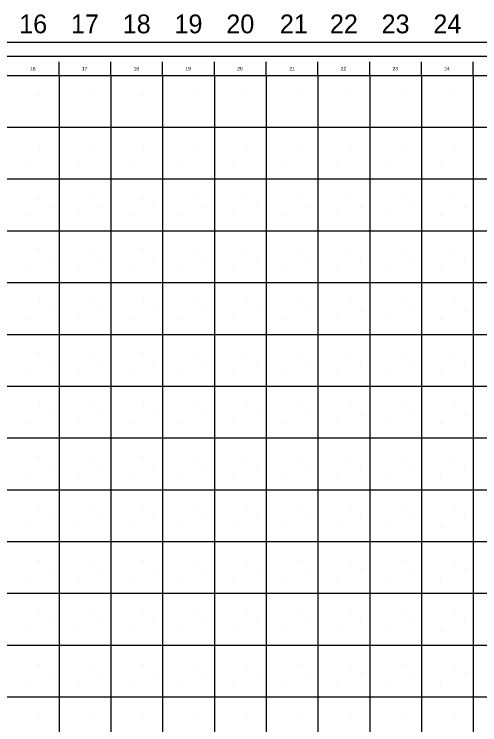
# Model space of a CAD drawing. Extents: x -0.05 to 1.19, y 0 to 0.86.
# Drawn here: x 0.5647 to 0.8795, y 0.3796 to 0.8598 of the extents above; entities that cross this region are included whole.
import ezdxf

# ---------------------------------------------------------------- set-up
doc = ezdxf.new("R2010")
doc.units = 0
for name, color, linetype in [('G-ANNO-NPLT', 7, 'Continuous'), ('G-ANNO-TEXT', 7, 'Continuous'), ('G-ANNO-TTLB', 7, 'Continuous'), ('G-ANNO-TTLB-GRID', 7, 'Continuous')]:
    doc.layers.add(name, color=color, linetype=linetype)

msp = doc.modelspace()

# ---------------------------------------------------------------- linework, layer by layer
at = {"layer": 'G-ANNO-NPLT'}
for p, q in [((0.58208, 0.80547), (0.58208, 0.80547)), ((0.61707, 0.80547), (0.61707, 0.80547)), ((0.65207, 0.80547), (0.65207, 0.80547)), ((0.68707, 0.80547), (0.68707, 0.80547)), ((0.72208, 0.80547), (0.72208, 0.80547)), ((0.75707, 0.80547), (0.75707, 0.80547)), ((0.79207, 0.80547), (0.79207, 0.80547)), ((0.82708, 0.80547), (0.82708, 0.80547)), ((0.86207, 0.80547), (0.86207, 0.80547)), ((0.58208, 0.77047), (0.58208, 0.77047)), ((0.61707, 0.77047), (0.61707, 0.77047)), ((0.65207, 0.77047), (0.65207, 0.77047)), ((0.68707, 0.77047), (0.68707, 0.77047)), ((0.72208, 0.77047), (0.72208, 0.77047)), ((0.75707, 0.77047), (0.75707, 0.77047)), ((0.79207, 0.77047), (0.79207, 0.77047)), ((0.82708, 0.77047), (0.82708, 0.77047)), ((0.86207, 0.77047), (0.86207, 0.77047)), ((0.57308, 0.75847), (0.57308, 0.75847)), ((0.60807, 0.75847), (0.60807, 0.75847)), ((0.64307, 0.75847), (0.64307, 0.75847)), ((0.67807, 0.75847), (0.67807, 0.75847)), ((0.71308, 0.75847), (0.71308, 0.75847)), ((0.74807, 0.75847), (0.74807, 0.75847)), ((0.78307, 0.75847), (0.78307, 0.75847)), ((0.81807, 0.75847), (0.81807, 0.75847)), ((0.85307, 0.75847), (0.85307, 0.75847)), ((0.58208, 0.73547), (0.58208, 0.73547)), ((0.61707, 0.73547), (0.61707, 0.73547)), ((0.65207, 0.73547), (0.65207, 0.73547)), ((0.68707, 0.73547), (0.68707, 0.73547)), ((0.72208, 0.73547), (0.72208, 0.73547)), ((0.75707, 0.73547), (0.75707, 0.73547)), ((0.79207, 0.73547), (0.79207, 0.73547)), ((0.82708, 0.73547), (0.82708, 0.73547)), ((0.86207, 0.73547), (0.86207, 0.73547)), ((0.58908, 0.72947), (0.58908, 0.72947)), ((0.62407, 0.72947), (0.62407, 0.72947)), ((0.65907, 0.72947), (0.65907, 0.72947)), ((0.69407, 0.72947), (0.69407, 0.72947)), ((0.72907, 0.72947), (0.72907, 0.72947)), ((0.76407, 0.72947), (0.76407, 0.72947)), ((0.79907, 0.72947), (0.79907, 0.72947)), ((0.83408, 0.72947), (0.83408, 0.72947)), ((0.86907, 0.72947), (0.86907, 0.72947)), ((0.57308, 0.72347), (0.57308, 0.72347)), ((0.60807, 0.72347), (0.60807, 0.72347)), ((0.64307, 0.72347), (0.64307, 0.72347)), ((0.67807, 0.72347), (0.67807, 0.72347)), ((0.71308, 0.72347), (0.71308, 0.72347)), ((0.74807, 0.72347), (0.74807, 0.72347)), ((0.78307, 0.72347), (0.78307, 0.72347)), ((0.81807, 0.72347), (0.81807, 0.72347)), ((0.85307, 0.72347), (0.85307, 0.72347)), ((0.58208, 0.70047), (0.58208, 0.70047)), ((0.61707, 0.70047), (0.61707, 0.70047)), ((0.65207, 0.70047), (0.65207, 0.70047)), ((0.68707, 0.70047), (0.68707, 0.70047)), ((0.72208, 0.70047), (0.72208, 0.70047)), ((0.75707, 0.70047), (0.75707, 0.70047)), ((0.79207, 0.70047), (0.79207, 0.70047)), ((0.82708, 0.70047), (0.82708, 0.70047)), ((0.86207, 0.70047), (0.86207, 0.70047)), ((0.58908, 0.69447), (0.58908, 0.69447)), ((0.62407, 0.69447), (0.62407, 0.69447)), ((0.65907, 0.69447), (0.65907, 0.69447)), ((0.69407, 0.69447), (0.69407, 0.69447)), ((0.72907, 0.69447), (0.72907, 0.69447)), ((0.76407, 0.69447), (0.76407, 0.69447)), ((0.79907, 0.69447), (0.79907, 0.69447)), ((0.83408, 0.69447), (0.83408, 0.69447)), ((0.86907, 0.69447), (0.86907, 0.69447)), ((0.57308, 0.68847), (0.57308, 0.68847)), ((0.60807, 0.68847), (0.60807, 0.68847)), ((0.64307, 0.68847), (0.64307, 0.68847)), ((0.67807, 0.68847), (0.67807, 0.68847)), ((0.71308, 0.68847), (0.71308, 0.68847)), ((0.74807, 0.68847), (0.74807, 0.68847)), ((0.78307, 0.68847), (0.78307, 0.68847)), ((0.81807, 0.68847), (0.81807, 0.68847)), ((0.85307, 0.68847), (0.85307, 0.68847)), ((0.58208, 0.66547), (0.58208, 0.66547)), ((0.61707, 0.66547), (0.61707, 0.66547)), ((0.65207, 0.66547), (0.65207, 0.66547)), ((0.68707, 0.66547), (0.68707, 0.66547)), ((0.72208, 0.66547), (0.72208, 0.66547)), ((0.75707, 0.66547), (0.75707, 0.66547)), ((0.79207, 0.66547), (0.79207, 0.66547)), ((0.82708, 0.66547), (0.82708, 0.66547)), ((0.86207, 0.66547), (0.86207, 0.66547)), ((0.58908, 0.65947), (0.58908, 0.65947)), ((0.62407, 0.65947), (0.62407, 0.65947)), ((0.65907, 0.65947), (0.65907, 0.65947)), ((0.69407, 0.65947), (0.69407, 0.65947)), ((0.72907, 0.65947), (0.72907, 0.65947)), ((0.76407, 0.65947), (0.76407, 0.65947)), ((0.79907, 0.65947), (0.79907, 0.65947)), ((0.83408, 0.65947), (0.83408, 0.65947)), ((0.86907, 0.65947), (0.86907, 0.65947)), ((0.57308, 0.65347), (0.57308, 0.65347)), ((0.60807, 0.65347), (0.60807, 0.65347)), ((0.64307, 0.65347), (0.64307, 0.65347)), ((0.67807, 0.65347), (0.67807, 0.65347)), ((0.71308, 0.65347), (0.71308, 0.65347)), ((0.74807, 0.65347), (0.74807, 0.65347)), ((0.78307, 0.65347), (0.78307, 0.65347)), ((0.81807, 0.65347), (0.81807, 0.65347)), ((0.85307, 0.65347), (0.85307, 0.65347)), ((0.58208, 0.63047), (0.58208, 0.63047)), ((0.61707, 0.63047), (0.61707, 0.63047)), ((0.65207, 0.63047), (0.65207, 0.63047)), ((0.68707, 0.63047), (0.68707, 0.63047)), ((0.72208, 0.63047), (0.72208, 0.63047)), ((0.75707, 0.63047), (0.75707, 0.63047)), ((0.79207, 0.63047), (0.79207, 0.63047)), ((0.82708, 0.63047), (0.82708, 0.63047)), ((0.86207, 0.63047), (0.86207, 0.63047)), ((0.58908, 0.62447), (0.58908, 0.62447)), ((0.62407, 0.62447), (0.62407, 0.62447)), ((0.65907, 0.62447), (0.65907, 0.62447)), ((0.69407, 0.62447), (0.69407, 0.62447)), ((0.72907, 0.62447), (0.72907, 0.62447)), ((0.76407, 0.62447), (0.76407, 0.62447)), ((0.79907, 0.62447), (0.79907, 0.62447)), ((0.83408, 0.62447), (0.83408, 0.62447)), ((0.86907, 0.62447), (0.86907, 0.62447)), ((0.57308, 0.61847), (0.57308, 0.61847)), ((0.60807, 0.61847), (0.60807, 0.61847)), ((0.64307, 0.61847), (0.64307, 0.61847)), ((0.67807, 0.61847), (0.67807, 0.61847)), ((0.71308, 0.61847), (0.71308, 0.61847)), ((0.74807, 0.61847), (0.74807, 0.61847)), ((0.78307, 0.61847), (0.78307, 0.61847)), ((0.81807, 0.61847), (0.81807, 0.61847)), ((0.85307, 0.61847), (0.85307, 0.61847)), ((0.58208, 0.59547), (0.58208, 0.59547)), ((0.61707, 0.59547), (0.61707, 0.59547)), ((0.65207, 0.59547), (0.65207, 0.59547)), ((0.68707, 0.59547), (0.68707, 0.59547)), ((0.72208, 0.59547), (0.72208, 0.59547)), ((0.75707, 0.59547), (0.75707, 0.59547)), ((0.79207, 0.59547), (0.79207, 0.59547)), ((0.82708, 0.59547), (0.82708, 0.59547)), ((0.86207, 0.59547), (0.86207, 0.59547)), ((0.58908, 0.58947), (0.58908, 0.58947)), ((0.62407, 0.58947), (0.62407, 0.58947)), ((0.65907, 0.58947), (0.65907, 0.58947)), ((0.69407, 0.58947), (0.69407, 0.58947)), ((0.72907, 0.58947), (0.72907, 0.58947)), ((0.76407, 0.58947), (0.76407, 0.58947)), ((0.79907, 0.58947), (0.79907, 0.58947)), ((0.83408, 0.58947), (0.83408, 0.58947)), ((0.86907, 0.58947), (0.86907, 0.58947)), ((0.57308, 0.58347), (0.57308, 0.58347)), ((0.60807, 0.58347), (0.60807, 0.58347)), ((0.64307, 0.58347), (0.64307, 0.58347)), ((0.67807, 0.58347), (0.67807, 0.58347)), ((0.71308, 0.58347), (0.71308, 0.58347)), ((0.74807, 0.58347), (0.74807, 0.58347)), ((0.78307, 0.58347), (0.78307, 0.58347)), ((0.81807, 0.58347), (0.81807, 0.58347)), ((0.85307, 0.58347), (0.85307, 0.58347)), ((0.58208, 0.56047), (0.58208, 0.56047)), ((0.61707, 0.56047), (0.61707, 0.56047)), ((0.65207, 0.56047), (0.65207, 0.56047)), ((0.68707, 0.56047), (0.68707, 0.56047)), ((0.72208, 0.56047), (0.72208, 0.56047)), ((0.75707, 0.56047), (0.75707, 0.56047)), ((0.79207, 0.56047), (0.79207, 0.56047)), ((0.82708, 0.56047), (0.82708, 0.56047)), ((0.86207, 0.56047), (0.86207, 0.56047)), ((0.58908, 0.55447), (0.58908, 0.55447)), ((0.62407, 0.55447), (0.62407, 0.55447)), ((0.65907, 0.55447), (0.65907, 0.55447)), ((0.69407, 0.55447), (0.69407, 0.55447)), ((0.72907, 0.55447), (0.72907, 0.55447)), ((0.76407, 0.55447), (0.76407, 0.55447)), ((0.79907, 0.55447), (0.79907, 0.55447)), ((0.83408, 0.55447), (0.83408, 0.55447)), ((0.86907, 0.55447), (0.86907, 0.55447)), ((0.57308, 0.54847), (0.57308, 0.54847)), ((0.60807, 0.54847), (0.60807, 0.54847)), ((0.64307, 0.54847), (0.64307, 0.54847)), ((0.67807, 0.54847), (0.67807, 0.54847)), ((0.71308, 0.54847), (0.71308, 0.54847)), ((0.74807, 0.54847), (0.74807, 0.54847)), ((0.78307, 0.54847), (0.78307, 0.54847)), ((0.81807, 0.54847), (0.81807, 0.54847)), ((0.85307, 0.54847), (0.85307, 0.54847)), ((0.58208, 0.52547), (0.58208, 0.52547)), ((0.61707, 0.52547), (0.61707, 0.52547)), ((0.65207, 0.52547), (0.65207, 0.52547)), ((0.68707, 0.52547), (0.68707, 0.52547)), ((0.72208, 0.52547), (0.72208, 0.52547)), ((0.75707, 0.52547), (0.75707, 0.52547)), ((0.79207, 0.52547), (0.79207, 0.52547)), ((0.82708, 0.52547), (0.82708, 0.52547)), ((0.86207, 0.52547), (0.86207, 0.52547)), ((0.58908, 0.51947), (0.58908, 0.51947)), ((0.62407, 0.51947), (0.62407, 0.51947)), ((0.65907, 0.51947), (0.65907, 0.51947)), ((0.69407, 0.51947), (0.69407, 0.51947)), ((0.72907, 0.51947), (0.72907, 0.51947)), ((0.76407, 0.51947), (0.76407, 0.51947)), ((0.79907, 0.51947), (0.79907, 0.51947)), ((0.83408, 0.51947), (0.83408, 0.51947)), ((0.86907, 0.51947), (0.86907, 0.51947)), ((0.57308, 0.51347), (0.57308, 0.51347)), ((0.60807, 0.51347), (0.60807, 0.51347)), ((0.64307, 0.51347), (0.64307, 0.51347)), ((0.67807, 0.51347), (0.67807, 0.51347)), ((0.71308, 0.51347), (0.71308, 0.51347)), ((0.74807, 0.51347), (0.74807, 0.51347)), ((0.78307, 0.51347), (0.78307, 0.51347)), ((0.81807, 0.51347), (0.81807, 0.51347)), ((0.85307, 0.51347), (0.85307, 0.51347)), ((0.58208, 0.49047), (0.58208, 0.49047)), ((0.61707, 0.49047), (0.61707, 0.49047)), ((0.65207, 0.49047), (0.65207, 0.49047)), ((0.68707, 0.49047), (0.68707, 0.49047)), ((0.72208, 0.49047), (0.72208, 0.49047)), ((0.75707, 0.49047), (0.75707, 0.49047)), ((0.79207, 0.49047), (0.79207, 0.49047)), ((0.82708, 0.49047), (0.82708, 0.49047)), ((0.86207, 0.49047), (0.86207, 0.49047)), ((0.58908, 0.48447), (0.58908, 0.48447)), ((0.62407, 0.48447), (0.62407, 0.48447)), ((0.65907, 0.48447), (0.65907, 0.48447)), ((0.69407, 0.48447), (0.69407, 0.48447)), ((0.72907, 0.48447), (0.72907, 0.48447)), ((0.76407, 0.48447), (0.76407, 0.48447)), ((0.79907, 0.48447), (0.79907, 0.48447)), ((0.83408, 0.48447), (0.83408, 0.48447)), ((0.86907, 0.48447), (0.86907, 0.48447)), ((0.57308, 0.47847), (0.57308, 0.47847)), ((0.60807, 0.47847), (0.60807, 0.47847)), ((0.64307, 0.47847), (0.64307, 0.47847)), ((0.67807, 0.47847), (0.67807, 0.47847)), ((0.71308, 0.47847), (0.71308, 0.47847)), ((0.74807, 0.47847), (0.74807, 0.47847)), ((0.78307, 0.47847), (0.78307, 0.47847)), ((0.81807, 0.47847), (0.81807, 0.47847)), ((0.85307, 0.47847), (0.85307, 0.47847)), ((0.58208, 0.45547), (0.58208, 0.45547)), ((0.61707, 0.45547), (0.61707, 0.45547)), ((0.65207, 0.45547), (0.65207, 0.45547)), ((0.68707, 0.45547), (0.68707, 0.45547)), ((0.72208, 0.45547), (0.72208, 0.45547)), ((0.75707, 0.45547), (0.75707, 0.45547)), ((0.79207, 0.45547), (0.79207, 0.45547)), ((0.82708, 0.45547), (0.82708, 0.45547)), ((0.86207, 0.45547), (0.86207, 0.45547)), ((0.58908, 0.44947), (0.58908, 0.44947)), ((0.62407, 0.44947), (0.62407, 0.44947)), ((0.65907, 0.44947), (0.65907, 0.44947)), ((0.69407, 0.44947), (0.69407, 0.44947)), ((0.72907, 0.44947), (0.72907, 0.44947)), ((0.76407, 0.44947), (0.76407, 0.44947)), ((0.79907, 0.44947), (0.79907, 0.44947)), ((0.83408, 0.44947), (0.83408, 0.44947)), ((0.86907, 0.44947), (0.86907, 0.44947)), ((0.57308, 0.44347), (0.57308, 0.44347)), ((0.60807, 0.44347), (0.60807, 0.44347)), ((0.64307, 0.44347), (0.64307, 0.44347)), ((0.67807, 0.44347), (0.67807, 0.44347)), ((0.71308, 0.44347), (0.71308, 0.44347)), ((0.74807, 0.44347), (0.74807, 0.44347)), ((0.78307, 0.44347), (0.78307, 0.44347)), ((0.81807, 0.44347), (0.81807, 0.44347)), ((0.85307, 0.44347), (0.85307, 0.44347)), ((0.58208, 0.42047), (0.58208, 0.42047)), ((0.61707, 0.42047), (0.61707, 0.42047)), ((0.65207, 0.42047), (0.65207, 0.42047)), ((0.68707, 0.42047), (0.68707, 0.42047)), ((0.72208, 0.42047), (0.72208, 0.42047)), ((0.75707, 0.42047), (0.75707, 0.42047)), ((0.79207, 0.42047), (0.79207, 0.42047)), ((0.82708, 0.42047), (0.82708, 0.42047)), ((0.86207, 0.42047), (0.86207, 0.42047)), ((0.58908, 0.41447), (0.58908, 0.41447)), ((0.62407, 0.41447), (0.62407, 0.41447)), ((0.65907, 0.41447), (0.65907, 0.41447)), ((0.69407, 0.41447), (0.69407, 0.41447)), ((0.72907, 0.41447), (0.72907, 0.41447)), ((0.76407, 0.41447), (0.76407, 0.41447)), ((0.79907, 0.41447), (0.79907, 0.41447)), ((0.83408, 0.41447), (0.83408, 0.41447)), ((0.86907, 0.41447), (0.86907, 0.41447)), ((0.57308, 0.40847), (0.57308, 0.40847)), ((0.60807, 0.40847), (0.60807, 0.40847)), ((0.64307, 0.40847), (0.64307, 0.40847)), ((0.67807, 0.40847), (0.67807, 0.40847)), ((0.71308, 0.40847), (0.71308, 0.40847)), ((0.74807, 0.40847), (0.74807, 0.40847)), ((0.78307, 0.40847), (0.78307, 0.40847)), ((0.81807, 0.40847), (0.81807, 0.40847)), ((0.85307, 0.40847), (0.85307, 0.40847)), ((0.58208, 0.38547), (0.58208, 0.38547)), ((0.61707, 0.38547), (0.61707, 0.38547)), ((0.65207, 0.38547), (0.65207, 0.38547)), ((0.68707, 0.38547), (0.68707, 0.38547)), ((0.72208, 0.38547), (0.72208, 0.38547)), ((0.75707, 0.38547), (0.75707, 0.38547)), ((0.79207, 0.38547), (0.79207, 0.38547)), ((0.82708, 0.38547), (0.82708, 0.38547)), ((0.86207, 0.38547), (0.86207, 0.38547))]:
    msp.add_line(p, q, dxfattribs=at)
msp.add_lwpolyline([(0.00952, 0.83147), (1.17948, 0.83147), (1.17948, 0.00952), (0.00952, 0.00952)], close=True, dxfattribs=at)
at = {"layer": 'G-ANNO-TEXT'}
for p, q in [((0.59508, 0.81847), (0.59508, 0.82753)), ((0.63007, 0.81847), (0.63007, 0.82753)), ((0.66507, 0.81847), (0.66507, 0.82753)), ((0.70008, 0.81847), (0.70008, 0.82753)), ((0.73507, 0.81847), (0.73507, 0.82753)), ((0.77007, 0.81847), (0.77007, 0.82753)), ((0.80507, 0.81847), (0.80507, 0.82753)), ((0.84008, 0.81847), (0.84008, 0.82753)), ((0.87507, 0.81847), (0.87507, 0.82753))]:
    msp.add_line(p, q, dxfattribs=at)
at = {"layer": 'G-ANNO-TTLB'}
for points in [[(0, 0.841), (1.189, 0.841), (1.189, 0), (0, 0)], [(0.03507, 0.81847), (1.17009, 0.81847), (1.17009, 0.01347), (0.03507, 0.01347)]]:
    msp.add_lwpolyline(points, close=True, dxfattribs=at)
at = {"layer": 'G-ANNO-TTLB-GRID'}
for p, q in [((0.59508, 0.81847), (0.59508, 0.01347)), ((0.63007, 0.81847), (0.63007, 0.01347)), ((0.66507, 0.81847), (0.66507, 0.01347)), ((0.70008, 0.81847), (0.70008, 0.01347)), ((0.73507, 0.81847), (0.73507, 0.01347)), ((0.77007, 0.81847), (0.77007, 0.01347)), ((0.80507, 0.81847), (0.80507, 0.01347)), ((0.84008, 0.81847), (0.84008, 0.01347)), ((0.87507, 0.81847), (0.87507, 0.01347)), ((0.03507, 0.78347), (1.17009, 0.78347)), ((0.03507, 0.74847), (1.17009, 0.74847)), ((0.03507, 0.71347), (1.17009, 0.71347)), ((0.03507, 0.67847), (1.17009, 0.67847)), ((0.03507, 0.64347), (1.17009, 0.64347)), ((0.03507, 0.60847), (1.17009, 0.60847)), ((0.03507, 0.57347), (1.12007, 0.57347)), ((0.03507, 0.53847), (1.12007, 0.53847)), ((0.03507, 0.50347), (1.12007, 0.50347)), ((0.03507, 0.46847), (1.12007, 0.46847)), ((0.03507, 0.43347), (1.12007, 0.43347)), ((0.03507, 0.39847), (1.12007, 0.39847))]:
    msp.add_line(p, q, dxfattribs=at)

# ---------------------------------------------------------------- texts
at = {"layer": 'G-ANNO-NPLT'}
for s, p in [('16', (0.56811, 0.8469)), ('17', (0.60311, 0.8469)), ('18', (0.6381, 0.8469)), ('19', (0.6731, 0.8469)), ('20', (0.70814, 0.8469)), ('21', (0.74434, 0.8469)), ('22', (0.77818, 0.8469)), ('23', (0.81311, 0.8469)), ('24', (0.84814, 0.8469))]:
    msp.add_text(s, height=0.0127, dxfattribs=at).set_placement(p)
at = {"layer": 'G-ANNO-TEXT'}
for s, p in [('16', (0.57547, 0.8218)), ('17', (0.61047, 0.8218)), ('18', (0.64547, 0.8218)), ('19', (0.68047, 0.8218)), ('20', (0.71547, 0.8218)), ('21', (0.75076, 0.8218)), ('22', (0.78548, 0.8218)), ('23', (0.82047, 0.8218)), ('24', (0.85548, 0.8218))]:
    msp.add_text(s, height=0.0024, dxfattribs=at).set_placement(p)

doc.saveas('drawing.dxf')
